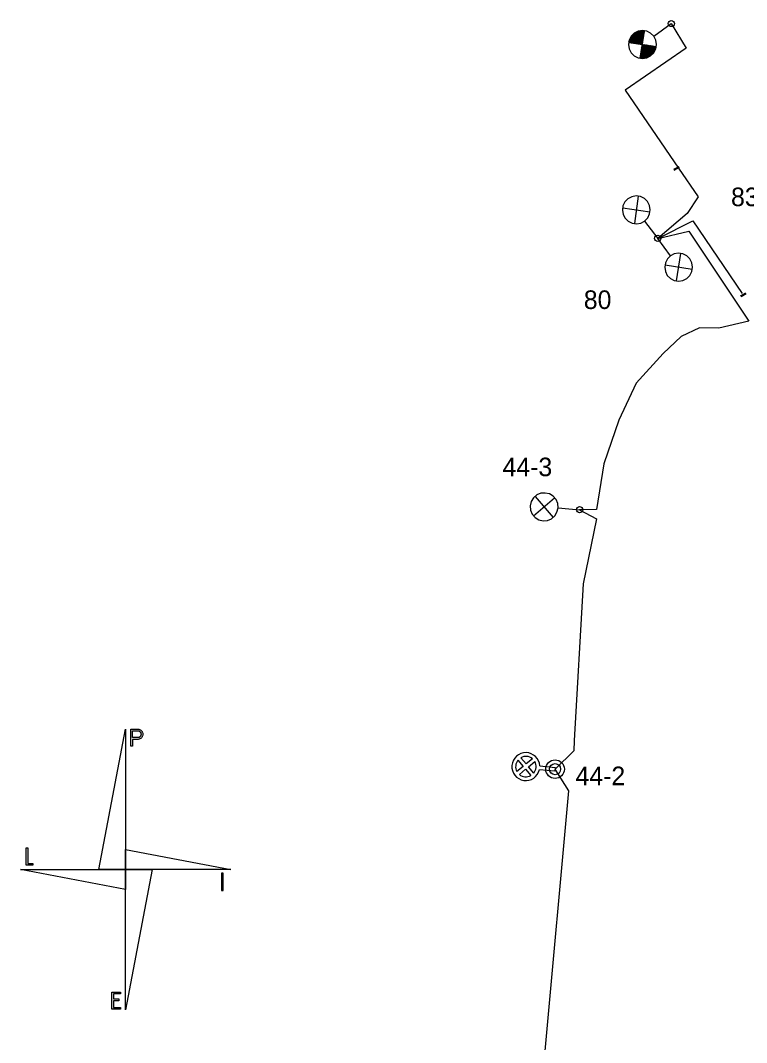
# Model space of a CAD drawing. Extents: x 25497851 to 25498523, y 6686544 to 6687372.
# Drawn here: x 25498180.5 to 25498297.7, y 6687207 to 6687372 of the extents above; entities that cross this region are included whole.
import ezdxf

# ---------------------------------------------------------------- set-up
doc = ezdxf.new("R2010")
doc.units = 0
for name, color, linetype in [('EL_CABLE_MAA', 7, 'Continuous'), ('KAAPELI', 7, 'Continuous'), ('KEYGWT_ANNOTATION', 7, 'Continuous'), ('MUU_UV-SUUNNITELMASYMBOLI', 7, 'Continuous'), ('PYLVAS', 7, 'Continuous'), ('Taso 1', 7, 'Continuous'), ('Taso 50', 7, 'Continuous'), ('VALAISIN', 7, 'Continuous')]:
    doc.layers.add(name, color=color, linetype=linetype)

msp = doc.modelspace()

# ---------------------------------------------------------------- linework, layer by layer
at = {"layer": 'EL_CABLE_MAA'}
for points in [[(25498285.58, 6687371.52), (25498287.96, 6687367.55), (25498278.11, 6687360.76), (25498286.76, 6687348.18)], [(25498286.76, 6687348.18), (25498289.94, 6687343.56), (25498288.15, 6687340.87), (25498283.39, 6687336.84)], [(25498283.39, 6687336.84), (25498289.08, 6687339.68), (25498297.01, 6687327.93)], [(25498283.39, 6687336.84), (25498288.4, 6687337.99), (25498298.11, 6687323.46), (25498293.24, 6687322.37), (25498290.14, 6687322.41), (25498287.2, 6687321), (25498284.25, 6687318.23), (25498279.91, 6687313.45), (25498277.1, 6687307.48), (25498274.67, 6687300.43), (25498273.49, 6687293.07), (25498270.78, 6687293.04)], [(25498270.78, 6687293.04), (25498273.51, 6687291.57), (25498271.36, 6687281.07), (25498269.91, 6687255.77), (25498269.86, 6687254.08), (25498266.81, 6687251.14)]]:
    msp.add_lwpolyline(points, dxfattribs=at)
at = {"layer": 'KAAPELI'}
msp.add_lwpolyline([(25498262.68, 6687204), (25498265.21, 6687205.67), (25498269.02, 6687247.64), (25498266.81, 6687251.15)], dxfattribs=at)
at = {"layer": 'MUU_UV-SUUNNITELMASYMBOLI'}
for p, q in [((25498181.36, 6687238.42), (25498181.63, 6687238.42)), ((25498181.36, 6687235.64), (25498181.36, 6687238.42)), ((25498181.63, 6687238.42), (25498181.63, 6687235.92)), ((25498182.46, 6687235.64), (25498181.36, 6687235.64)), ((25498181.63, 6687235.92), (25498182.46, 6687235.92)), ((25498182.46, 6687235.92), (25498182.46, 6687235.64)), ((25498195.22, 6687215.16), (25498196.6, 6687215.16)), ((25498195.22, 6687212.38), (25498195.22, 6687215.16)), ((25498196.6, 6687214.88), (25498195.5, 6687214.88)), ((25498195.5, 6687214.88), (25498195.5, 6687214.04)), ((25498196.6, 6687215.16), (25498196.6, 6687214.88)), ((25498195.5, 6687214.04), (25498196.33, 6687214.04)), ((25498196.33, 6687213.76), (25498195.5, 6687213.76)), ((25498195.5, 6687213.76), (25498195.5, 6687212.66)), ((25498196.33, 6687214.04), (25498196.33, 6687213.76)), ((25498196.6, 6687212.38), (25498195.22, 6687212.38)), ((25498195.5, 6687212.66), (25498196.6, 6687212.66)), ((25498196.6, 6687212.66), (25498196.6, 6687212.38))]:
    msp.add_line(p, q, dxfattribs=at)
for points in [[(25498193.13, 6687234.96), (25498197.44, 6687257.6), (25498197.44, 6687234.96)], [(25498197.44, 6687238.18), (25498214.42, 6687234.96), (25498197.44, 6687234.96)], [(25498197.44, 6687231.73), (25498180.46, 6687234.96), (25498197.44, 6687234.96)], [(25498201.74, 6687234.96), (25498197.44, 6687212.31), (25498197.44, 6687234.96)]]:
    msp.add_lwpolyline(points, close=True, dxfattribs=at)
for points in [[(25498198.29, 6687254.84), (25498198.29, 6687257.61), (25498199.39, 6687257.61)], [(25498199.39, 6687257.61), (25498199.48, 6687257.61), (25498199.56, 6687257.6), (25498199.64, 6687257.57), (25498199.73, 6687257.54), (25498199.8, 6687257.5), (25498199.88, 6687257.46), (25498199.94, 6687257.4), (25498200, 6687257.34), (25498200.06, 6687257.27), (25498200.11, 6687257.2), (25498200.14, 6687257.12), (25498200.18, 6687257.04), (25498200.2, 6687256.96), (25498200.21, 6687256.87), (25498200.22, 6687256.79), (25498200.21, 6687256.7), (25498200.2, 6687256.61), (25498200.18, 6687256.53), (25498200.14, 6687256.45), (25498200.11, 6687256.37), (25498200.06, 6687256.3), (25498200, 6687256.23), (25498199.94, 6687256.17), (25498199.88, 6687256.12), (25498199.8, 6687256.07), (25498199.73, 6687256.03), (25498199.64, 6687256), (25498199.56, 6687255.98), (25498199.48, 6687255.96), (25498199.39, 6687255.96)], [(25498199.39, 6687255.96), (25498198.56, 6687255.96), (25498198.56, 6687254.84), (25498198.29, 6687254.84)], [(25498198.56, 6687256.24), (25498198.56, 6687257.34), (25498199.39, 6687257.34)], [(25498199.39, 6687256.24), (25498198.56, 6687256.24)], [(25498199.39, 6687257.34), (25498199.45, 6687257.33), (25498199.5, 6687257.33), (25498199.56, 6687257.31), (25498199.61, 6687257.29), (25498199.67, 6687257.26), (25498199.71, 6687257.23), (25498199.76, 6687257.2), (25498199.8, 6687257.16), (25498199.84, 6687257.11), (25498199.87, 6687257.06), (25498199.89, 6687257.01), (25498199.91, 6687256.96), (25498199.93, 6687256.9), (25498199.94, 6687256.84), (25498199.94, 6687256.79), (25498199.94, 6687256.73), (25498199.93, 6687256.67), (25498199.91, 6687256.62), (25498199.89, 6687256.56), (25498199.87, 6687256.51), (25498199.84, 6687256.46), (25498199.8, 6687256.42), (25498199.76, 6687256.38), (25498199.71, 6687256.34), (25498199.67, 6687256.31), (25498199.61, 6687256.28), (25498199.56, 6687256.26), (25498199.5, 6687256.25), (25498199.45, 6687256.24), (25498199.39, 6687256.24)], [(25498212.93, 6687231.56), (25498213.2, 6687231.56), (25498213.2, 6687234.36), (25498212.93, 6687234.36), (25498212.93, 6687231.56)]]:
    msp.add_lwpolyline(points, dxfattribs=at)
at = {"layer": 'PYLVAS'}
for radius in [1.5, 0.9]:
    msp.add_circle((25498266.81, 6687251.15), radius, dxfattribs=at)
at = {"layer": 'Taso 1'}
for p, q in [((25498282.75, 6687369.47), (25498285.58, 6687371.52)), ((25498280.58, 6687365.95), (25498281.28, 6687370.34)), ((25498278.74, 6687368.49), (25498283.13, 6687367.8)), ((25498285.99, 6687347.99), (25498286.84, 6687348.47)), ((25498286.06, 6687347.87), (25498286.91, 6687348.35)), ((25498280.25, 6687343.64), (25498279.62, 6687339.24)), ((25498277.73, 6687341.75), (25498282.13, 6687341.13)), ((25498281.28, 6687339.64), (25498283.39, 6687336.84)), ((25498285.44, 6687334.01), (25498283.39, 6687336.84)), ((25498286.42, 6687329.99), (25498287.11, 6687334.38)), ((25498288.96, 6687331.84), (25498284.57, 6687332.54)), ((25498296.78, 6687327.55), (25498297.62, 6687328.04)), ((25498296.85, 6687327.43), (25498297.69, 6687327.92)), ((25498263.35, 6687292.05), (25498266.73, 6687294.93)), ((25498263.6, 6687295.18), (25498266.49, 6687291.8)), ((25498267.29, 6687293.31), (25498270.78, 6687293.04))]:
    msp.add_line(p, q, dxfattribs=at)
for points in [[(25498279.11, 6687366.82), (25498279.61, 6687366.33), (25498280.24, 6687366.01), (25498280.93, 6687365.9), (25498281.63, 6687366.01), (25498282.25, 6687366.32), (25498282.75, 6687366.82), (25498283.07, 6687367.45), (25498283.18, 6687368.14), (25498283.07, 6687368.84), (25498282.75, 6687369.47), (25498282.25, 6687369.96), (25498281.63, 6687370.28), (25498280.93, 6687370.39), (25498280.24, 6687370.28), (25498279.61, 6687369.97), (25498279.11, 6687369.47), (25498278.79, 6687368.84), (25498278.68, 6687368.15), (25498278.79, 6687367.45)], [(25498278.58, 6687343.24), (25498278.09, 6687342.73), (25498277.78, 6687342.1), (25498277.68, 6687341.4), (25498277.81, 6687340.71), (25498278.13, 6687340.09), (25498278.64, 6687339.6), (25498279.27, 6687339.29), (25498279.97, 6687339.19), (25498280.66, 6687339.31), (25498281.28, 6687339.64), (25498281.77, 6687340.14), (25498282.08, 6687340.78), (25498282.18, 6687341.47), (25498282.06, 6687342.17), (25498281.73, 6687342.79), (25498281.23, 6687343.28), (25498280.6, 6687343.59), (25498279.9, 6687343.69), (25498279.21, 6687343.57)], [(25498288.09, 6687330.37), (25498288.58, 6687330.87), (25498288.9, 6687331.49), (25498289.01, 6687332.19), (25498288.9, 6687332.88), (25498288.59, 6687333.51), (25498288.09, 6687334.01), (25498287.46, 6687334.33), (25498286.77, 6687334.44), (25498286.07, 6687334.33), (25498285.44, 6687334.01), (25498284.95, 6687333.51), (25498284.63, 6687332.88), (25498284.52, 6687332.19), (25498284.63, 6687331.49), (25498284.94, 6687330.87), (25498285.44, 6687330.37), (25498286.07, 6687330.05), (25498286.76, 6687329.94), (25498287.46, 6687330.05)], [(25498262.8, 6687293.67), (25498262.86, 6687292.97), (25498263.13, 6687292.31), (25498263.58, 6687291.78), (25498264.18, 6687291.41), (25498264.87, 6687291.25), (25498265.57, 6687291.3), (25498266.22, 6687291.57), (25498266.75, 6687292.03), (25498267.12, 6687292.63), (25498267.29, 6687293.31), (25498267.23, 6687294.02), (25498266.96, 6687294.67), (25498266.51, 6687295.2), (25498265.91, 6687295.57), (25498265.22, 6687295.73), (25498264.52, 6687295.68), (25498263.87, 6687295.41), (25498263.33, 6687294.95), (25498262.97, 6687294.35)]]:
    msp.add_lwpolyline(points, close=True, dxfattribs=at)
for centre in [(25498285.58, 6687371.52), (25498283.39, 6687336.84), (25498270.78, 6687293.04)]:
    msp.add_circle(centre, 0.5, dxfattribs=at)
at = {"layer": 'Taso 50'}
for p, q in [((25498280.58, 6687368.2), (25498279.44, 6687369.78)), ((25498280.65, 6687368.19), (25498279.48, 6687369.81)), ((25498280.72, 6687368.18), (25498279.52, 6687369.84)), ((25498280.79, 6687368.17), (25498279.56, 6687369.87)), ((25498280.86, 6687368.16), (25498279.57, 6687369.94)), ((25498280.93, 6687368.14), (25498279.61, 6687369.97)), ((25498280.94, 6687368.21), (25498279.65, 6687369.99)), ((25498280.95, 6687368.28), (25498279.72, 6687369.98)), ((25498280.96, 6687368.35), (25498279.76, 6687370.01)), ((25498280.98, 6687368.42), (25498279.8, 6687370.04)), ((25498280.99, 6687368.49), (25498279.84, 6687370.07)), ((25498281, 6687368.56), (25498279.88, 6687370.1)), ((25498281.01, 6687368.63), (25498279.92, 6687370.13)), ((25498281.02, 6687368.7), (25498279.99, 6687370.12)), ((25498281.03, 6687368.77), (25498280.03, 6687370.15)), ((25498281.04, 6687368.84), (25498280.07, 6687370.18)), ((25498281.05, 6687368.91), (25498280.11, 6687370.21)), ((25498281.06, 6687368.98), (25498280.15, 6687370.24)), ((25498281.08, 6687369.05), (25498280.19, 6687370.27)), ((25498281.09, 6687369.12), (25498280.24, 6687370.28)), ((25498281.1, 6687369.19), (25498280.3, 6687370.28)), ((25498281.11, 6687369.26), (25498280.37, 6687370.27)), ((25498281.12, 6687369.33), (25498280.41, 6687370.3)), ((25498281.13, 6687369.4), (25498280.48, 6687370.29)), ((25498281.14, 6687369.47), (25498280.52, 6687370.32)), ((25498281.15, 6687369.54), (25498280.58, 6687370.33)), ((25498281.16, 6687369.61), (25498280.63, 6687370.34)), ((25498281.17, 6687369.68), (25498280.7, 6687370.33)), ((25498281.19, 6687369.75), (25498280.74, 6687370.36)), ((25498281.2, 6687369.82), (25498280.81, 6687370.35)), ((25498281.21, 6687369.89), (25498280.86, 6687370.38)), ((25498281.22, 6687369.96), (25498280.92, 6687370.36)), ((25498281.23, 6687370.03), (25498280.97, 6687370.39)), ((25498281.24, 6687370.1), (25498281.04, 6687370.38)), ((25498281.25, 6687370.17), (25498281.11, 6687370.37)), ((25498281.26, 6687370.24), (25498281.17, 6687370.36)), ((25498278.84, 6687368.48), (25498278.75, 6687368.6)), ((25498278.91, 6687368.47), (25498278.76, 6687368.67)), ((25498279.12, 6687368.43), (25498278.79, 6687368.88)), ((25498278.98, 6687368.45), (25498278.8, 6687368.7)), ((25498279.05, 6687368.44), (25498278.81, 6687368.77)), ((25498279.19, 6687368.42), (25498278.83, 6687368.91)), ((25498279.26, 6687368.41), (25498278.87, 6687368.94)), ((25498279.32, 6687368.4), (25498278.88, 6687369.01)), ((25498279.39, 6687368.39), (25498278.92, 6687369.04)), ((25498279.46, 6687368.38), (25498278.94, 6687369.1)), ((25498279.53, 6687368.37), (25498278.98, 6687369.13)), ((25498279.6, 6687368.35), (25498278.99, 6687369.2)), ((25498279.67, 6687368.34), (25498279.03, 6687369.23)), ((25498279.74, 6687368.33), (25498279.04, 6687369.3)), ((25498279.81, 6687368.32), (25498279.08, 6687369.33)), ((25498279.88, 6687368.31), (25498279.09, 6687369.4)), ((25498279.95, 6687368.3), (25498279.11, 6687369.47)), ((25498280.02, 6687368.29), (25498279.14, 6687369.5)), ((25498280.09, 6687368.28), (25498279.18, 6687369.53)), ((25498280.16, 6687368.27), (25498279.22, 6687369.56)), ((25498280.23, 6687368.26), (25498279.26, 6687369.59)), ((25498280.3, 6687368.24), (25498279.3, 6687369.62)), ((25498280.37, 6687368.23), (25498279.34, 6687369.65)), ((25498280.44, 6687368.22), (25498279.36, 6687369.72)), ((25498280.51, 6687368.21), (25498279.4, 6687369.75)), ((25498282.25, 6687366.32), (25498280.93, 6687368.15)), ((25498282.29, 6687366.35), (25498281, 6687368.13)), ((25498281.07, 6687368.12), (25498282.31, 6687366.42)), ((25498281.14, 6687368.11), (25498282.35, 6687366.45)), ((25498280.67, 6687366.47), (25498281.05, 6687365.94)), ((25498280.68, 6687367.72), (25498280.68, 6687367.72)), ((25498280.68, 6687366.54), (25498281.12, 6687365.93)), ((25498280.69, 6687366.61), (25498281.16, 6687365.96)), ((25498280.7, 6687366.68), (25498281.23, 6687365.95)), ((25498280.71, 6687366.75), (25498281.27, 6687365.98)), ((25498280.72, 6687366.82), (25498281.34, 6687365.97)), ((25498280.73, 6687366.89), (25498281.38, 6687366)), ((25498280.74, 6687366.96), (25498281.45, 6687365.99)), ((25498280.75, 6687367.03), (25498281.49, 6687366.02)), ((25498280.77, 6687367.1), (25498281.56, 6687366)), ((25498280.78, 6687367.17), (25498281.6, 6687366.03)), ((25498280.79, 6687367.24), (25498281.67, 6687366.02)), ((25498281.71, 6687366.05), (25498280.8, 6687367.31)), ((25498281.75, 6687366.08), (25498280.81, 6687367.38)), ((25498281.79, 6687366.11), (25498280.82, 6687367.45)), ((25498281.83, 6687366.14), (25498280.83, 6687367.52)), ((25498280.84, 6687367.59), (25498281.87, 6687366.17)), ((25498280.86, 6687367.73), (25498281.98, 6687366.19)), ((25498281.94, 6687366.17), (25498280.86, 6687367.66)), ((25498282.06, 6687366.25), (25498280.89, 6687367.87)), ((25498282.1, 6687366.28), (25498280.9, 6687367.94)), ((25498282.14, 6687366.31), (25498280.91, 6687368)), ((25498282.02, 6687366.22), (25498280.91, 6687367.75)), ((25498282.21, 6687366.29), (25498280.92, 6687368.07)), ((25498281.21, 6687368.1), (25498282.39, 6687366.48)), ((25498281.28, 6687368.09), (25498282.43, 6687366.51)), ((25498281.35, 6687368.08), (25498282.47, 6687366.54)), ((25498281.42, 6687368.07), (25498282.5, 6687366.57)), ((25498281.49, 6687368.06), (25498282.52, 6687366.64)), ((25498281.56, 6687368.05), (25498282.56, 6687366.67)), ((25498281.63, 6687368.03), (25498282.6, 6687366.7)), ((25498281.7, 6687368.02), (25498282.64, 6687366.73)), ((25498281.77, 6687368.01), (25498282.65, 6687366.8)), ((25498281.84, 6687368), (25498282.69, 6687366.83)), ((25498281.91, 6687367.99), (25498282.73, 6687366.86)), ((25498281.98, 6687367.98), (25498282.77, 6687366.89)), ((25498282.05, 6687367.97), (25498282.78, 6687366.96)), ((25498282.12, 6687367.96), (25498282.82, 6687366.99)), ((25498282.19, 6687367.95), (25498282.83, 6687367.06)), ((25498282.26, 6687367.93), (25498282.88, 6687367.08)), ((25498282.33, 6687367.92), (25498282.89, 6687367.15)), ((25498282.4, 6687367.91), (25498282.93, 6687367.18)), ((25498282.47, 6687367.9), (25498282.94, 6687367.25)), ((25498282.54, 6687367.89), (25498282.98, 6687367.28)), ((25498282.61, 6687367.88), (25498282.99, 6687367.35)), ((25498282.68, 6687367.87), (25498283.03, 6687367.38)), ((25498282.75, 6687367.86), (25498283.04, 6687367.45)), ((25498282.82, 6687367.85), (25498283.05, 6687367.52)), ((25498282.89, 6687367.83), (25498283.09, 6687367.55)), ((25498282.96, 6687367.82), (25498283.1, 6687367.62)), ((25498283.03, 6687367.81), (25498283.11, 6687367.69)), ((25498280.6, 6687366.05), (25498280.66, 6687365.97)), ((25498280.61, 6687366.12), (25498280.76, 6687365.92)), ((25498280.62, 6687366.19), (25498280.83, 6687365.91)), ((25498280.63, 6687366.26), (25498280.87, 6687365.94)), ((25498280.64, 6687366.33), (25498280.94, 6687365.92)), ((25498280.65, 6687366.4), (25498281.01, 6687365.91))]:
    msp.add_line(p, q, dxfattribs=at)
at = {"layer": 'VALAISIN'}
for p, q in [((25498260.81, 6687252.61), (25498261.66, 6687251.6)), ((25498262.12, 6687251.98), (25498261.27, 6687252.99)), ((25498263.14, 6687252.83), (25498262.12, 6687251.98)), ((25498261.66, 6687251.6), (25498260.65, 6687250.75)), ((25498261.04, 6687250.29), (25498262.05, 6687251.14)), ((25498262.05, 6687251.14), (25498262.9, 6687250.12)), ((25498262.51, 6687251.52), (25498263.52, 6687252.37)), ((25498263.36, 6687250.51), (25498262.51, 6687251.52)), ((25498266.78, 6687250.84), (25498264.28, 6687251.06)), ((25498264.33, 6687251.66), (25498266.83, 6687251.44)), ((25498266.83, 6687251.44), (25498266.78, 6687250.84))]:
    msp.add_line(p, q, dxfattribs=at)
for radius, start, end in [(2.25, 2.6413, 174.979), (1.65, 140.4547, 174.979), (1.65, 50.4547, 119.5033), (2.25, 174.979, 347.3167), (1.65, 174.979, 209.5033), (1.65, 320.4547, 354.979), (1.65, 354.979, 29.5033), (1.65, 230.4547, 299.5033)]:
    msp.add_arc((25498262.09, 6687251.56), radius, start, end, dxfattribs=at)

# ---------------------------------------------------------------- texts
at = {"layer": 'KEYGWT_ANNOTATION'}
for s, p in [('83', (25498295.23, 6687342.04)), ('80', (25498271.45, 6687325.44)), ('44-3', (25498258.32, 6687298.44)), ('44-2', (25498270.11, 6687248.56))]:
    msp.add_text(s, height=3, dxfattribs=at).set_placement(p)

doc.saveas('drawing.dxf')
